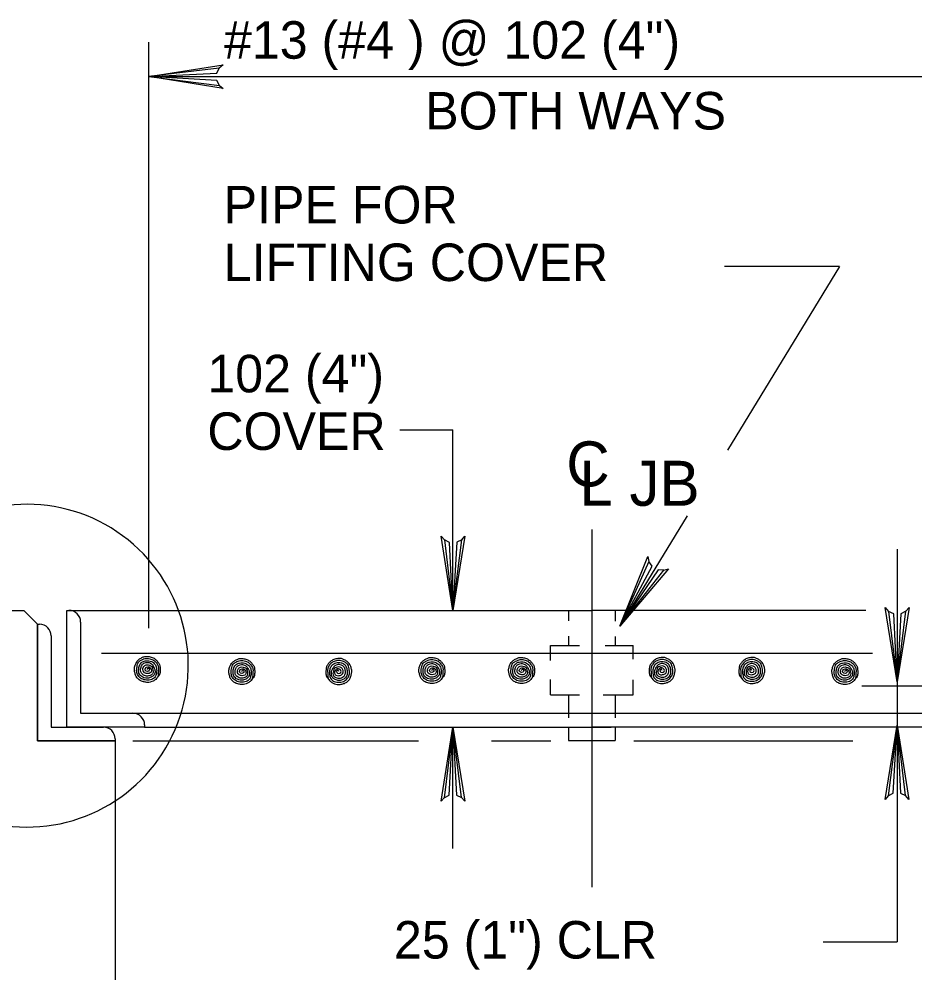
# Model space of a CAD drawing. Extents: x 638455 to 640199, y 298558 to 299152.
# Drawn here: x 638622.1 to 638702.3, y 298765.3 to 298851.3 of the extents above; entities that cross this region are included whole.
import ezdxf

# ---------------------------------------------------------------- set-up
doc = ezdxf.new("R2010")
doc.units = 0
for name, color, linetype in [('1', 7, 'Continuous'), ('2', 7, 'Continuous'), ('3', 7, 'Continuous')]:
    doc.layers.add(name, color=color, linetype=linetype)

msp = doc.modelspace()

# ---------------------------------------------------------------- linework, layer by layer
at = {"layer": '1'}
msp.add_arc((638622.784, 298793.392), 14.456, 185.43869, 133.00871, dxfattribs=at)
at = {"layer": '2'}
for p, q in [((638633.704, 298796.768), (638633.704, 298849.247)), ((638633.704, 298846.161), (638713.153, 298846.161)), ((638695.59, 298829.162), (638685.289, 298829.162)), ((638695.59, 298829.162), (638685.554, 298812.708)), ((638656.187, 298814.519), (638660.96, 298814.519)), ((638660.96, 298798.35), (638660.96, 298814.519)), ((638681.959, 298806.814), (638675.923, 298796.918)), ((638673.404, 298805.586), (638673.404, 298773.557)), ((638700.757, 298803.819), (638700.757, 298791.94)), ((638613.326, 298798.332), (638622.491, 298798.332)), ((638622.491, 298798.332), (638623.722, 298797.101)), ((638626.359, 298798.35), (638626.545, 298798.35)), ((638626.359, 298798.35), (638673.404, 298798.35)), ((638647.242, 298798.35), (638663.399, 298798.35)), ((638671.322, 298798.35), (638671.322, 298797.415)), ((638697.969, 298798.35), (638673.404, 298798.35)), ((638675.485, 298798.35), (638675.485, 298797.372)), ((638623.722, 298797.101), (638623.908, 298797.101)), ((638623.722, 298797.101), (638623.722, 298786.647)), ((638671.322, 298796.038), (638671.322, 298795.198)), ((638669.688, 298793.844), (638669.688, 298795.198)), ((638669.688, 298795.198), (638672.312, 298795.198)), ((638674.591, 298795.198), (638677.119, 298795.198)), ((638675.485, 298795.995), (638675.485, 298795.198)), ((638677.119, 298793.973), (638677.119, 298795.198)), ((638629.46, 298794.517), (638698.566, 298794.517)), ((638669.688, 298790.789), (638669.688, 298792.167)), ((638677.119, 298790.789), (638677.119, 298792.123)), ((638700.757, 298791.94), (638700.757, 298768.654)), ((638697.611, 298791.581), (638703.104, 298791.581)), ((638669.688, 298790.789), (638672.312, 298790.789)), ((638671.322, 298790.789), (638671.322, 298788.725)), ((638674.419, 298790.789), (638677.119, 298790.789)), ((638675.485, 298790.789), (638675.485, 298788.725)), ((638632.283, 298789.127), (638714.524, 298789.127)), ((638633.328, 298788.081), (638633.328, 298787.896)), ((638633.328, 298787.896), (638673.404, 298787.896)), ((638635.768, 298787.896), (638647.886, 298787.896)), ((638654.211, 298787.896), (638663.399, 298787.896)), ((638660.96, 298777.023), (638660.96, 298787.896)), ((638671.322, 298787.896), (638671.322, 298786.682)), ((638671.661, 298787.896), (638675.146, 298787.896)), ((638713.479, 298787.896), (638673.404, 298787.896)), ((638675.485, 298787.896), (638675.485, 298786.682)), ((638623.722, 298786.647), (638630.692, 298786.647)), ((638630.692, 298786.832), (638630.692, 298786.647)), ((638630.692, 298786.647), (638630.692, 298765.256)), ((638632.283, 298786.647), (638657.865, 298786.647)), ((638664.4, 298786.647), (638669.732, 298786.647)), ((638671.322, 298786.682), (638675.485, 298786.682)), ((638677.17, 298786.647), (638696.788, 298786.647)), ((638694.14, 298768.654), (638700.757, 298768.654))]:
    msp.add_line(p, q, dxfattribs=at)
for points in [[(638640.035, 298845.365), (638639.797, 298845.824), (638633.704, 298846.161), (638640.035, 298845.365), (638640.358, 298845.087), (638633.704, 298846.161), (638639.794, 298846.46), (638640.015, 298846.913), (638633.704, 298846.161), (638640.358, 298847.218), (638640.015, 298846.913)], [(638661.756, 298804.678), (638661.297, 298804.442), (638660.96, 298798.35), (638661.756, 298804.678), (638662.034, 298805.003), (638660.96, 298798.35), (638660.661, 298804.44), (638660.205, 298804.66), (638660.96, 298798.35), (638659.903, 298805.003), (638660.205, 298804.66)], [(638679.86, 298801.938), (638679.345, 298801.97), (638675.923, 298796.918), (638679.86, 298801.938), (638680.263, 298802.073), (638675.923, 298796.918), (638678.796, 298802.293), (638678.521, 298802.718), (638675.923, 298796.918), (638678.437, 298803.166), (638678.521, 298802.718)], [(638701.553, 298798.267), (638701.094, 298798.032), (638700.757, 298791.94), (638701.553, 298798.267), (638701.829, 298798.593), (638700.757, 298791.94), (638700.458, 298798.026), (638700.002, 298798.25), (638700.757, 298791.94), (638699.7, 298798.593), (638700.002, 298798.25)], [(638633.328, 298787.896), (638626.359, 298787.896), (638626.359, 298798.35)], [(638630.692, 298786.647), (638623.722, 298786.647), (638623.722, 298797.101)], [(638627.59, 298797.304), (638627.59, 298789.127), (638632.283, 298789.127)], [(638624.953, 298796.056), (638624.953, 298787.878), (638629.647, 298787.878)], [(638660.167, 298781.565), (638660.623, 298781.803), (638660.96, 298787.896), (638660.167, 298781.565), (638659.889, 298781.242), (638660.96, 298787.896), (638661.262, 298781.806), (638661.715, 298781.585), (638660.96, 298787.896), (638662.017, 298781.242), (638661.715, 298781.585)], [(638699.965, 298781.739), (638700.42, 298781.974), (638700.757, 298788.07), (638699.965, 298781.739), (638699.686, 298781.414), (638700.757, 298788.07), (638701.06, 298781.98), (638701.512, 298781.756), (638700.757, 298788.07), (638701.814, 298781.414), (638701.512, 298781.756)]]:
    msp.add_lwpolyline(points, dxfattribs=at)
for centre in [(638626.546, 298797.304), (638623.909, 298796.055), (638632.283, 298788.082), (638629.646, 298786.833)]:
    msp.add_arc(centre, 1.045, 0, 90, dxfattribs=at)
for points in [[(638633.572, 298793.057), (638633.63, 298793.174), (638633.72, 298793.162), (638633.738, 298792.979), (638633.578, 298792.88), (638633.381, 298792.979), (638633.389, 298793.162), (638633.497, 298793.273), (638633.72, 298793.29), (638633.871, 298793.174), (638633.947, 298792.988), (638633.836, 298792.738), (638633.595, 298792.683), (638633.328, 298792.764), (638633.183, 298792.932), (638633.203, 298793.22), (638633.337, 298793.403), (638633.578, 298793.47), (638633.79, 298793.424), (638633.97, 298793.316), (638634.045, 298793.13), (638634.089, 298792.889), (638634.036, 298792.665), (638633.827, 298792.523), (638633.505, 298792.462), (638633.157, 298792.605), (638632.983, 298792.845), (638632.983, 298793.174), (638633.096, 298793.455), (638633.337, 298793.644), (638633.72, 298793.664), (638633.99, 298793.513), (638634.156, 298793.249), (638634.254, 298792.979), (638634.211, 298792.648), (638633.99, 298792.416), (638633.673, 298792.282), (638633.171, 298792.363), (638632.855, 298792.639), (638632.788, 298793.023), (638632.855, 298793.403), (638633.073, 298793.696), (638633.366, 298793.815), (638633.827, 298793.807), (638634.188, 298793.598), (638634.362, 298793.29), (638634.406, 298792.965), (638634.377, 298792.683), (638634.263, 298792.381), (638633.97, 298792.166), (638633.488, 298792.099), (638633.058, 298792.221), (638632.741, 298792.514), (638632.614, 298792.863), (638632.646, 298793.304), (638632.788, 298793.719), (638633.029, 298793.894), (638633.453, 298794.045), (638633.894, 298793.981), (638634.202, 298793.839), (638634.437, 298793.566), (638634.562, 298793.281), (638634.562, 298792.979), (638634.548, 298792.648), (638634.472, 298792.34), (638634.319, 298792.166), (638634.077, 298792.015), (638633.836, 298791.925), (638633.595, 298791.89), (638633.29, 298791.934), (638632.983, 298792.032), (638632.721, 298792.23), (638632.538, 298792.48), (638632.448, 298792.79), (638632.405, 298793.086), (638632.471, 298793.424), (638632.591, 298793.696), (638632.808, 298793.946), (638633.073, 298794.115), (638633.337, 298794.213), (638633.648, 298794.222), (638634.014, 298794.135), (638634.319, 298793.946), (638634.504, 298793.749), (638634.661, 298793.499), (638634.713, 298793.237), (638634.722, 298792.932), (638634.661, 298792.605), (638634.562, 298792.451), (638634.362, 298792.23)], [(638642.04, 298792.869), (638642.098, 298792.985), (638642.188, 298792.973), (638642.206, 298792.79), (638642.046, 298792.692), (638641.848, 298792.79), (638641.857, 298792.973), (638641.964, 298793.084), (638642.188, 298793.101), (638642.339, 298792.985), (638642.415, 298792.799), (638642.304, 298792.549), (638642.063, 298792.494), (638641.796, 298792.575), (638641.651, 298792.744), (638641.671, 298793.028), (638641.805, 298793.211), (638642.046, 298793.281), (638642.258, 298793.235), (638642.438, 298793.127), (638642.513, 298792.941), (638642.557, 298792.7), (638642.505, 298792.477), (638642.295, 298792.335), (638641.973, 298792.271), (638641.625, 298792.416), (638641.451, 298792.654), (638641.451, 298792.985), (638641.564, 298793.266), (638641.805, 298793.452), (638642.188, 298793.476), (638642.458, 298793.325), (638642.624, 298793.061), (638642.723, 298792.79), (638642.679, 298792.459), (638642.458, 298792.227), (638642.142, 298792.093), (638641.639, 298792.175), (638641.323, 298792.451), (638641.256, 298792.834), (638641.323, 298793.211), (638641.54, 298793.507), (638641.834, 298793.627), (638642.295, 298793.618), (638642.656, 298793.409), (638642.83, 298793.101), (638642.874, 298792.776), (638642.841, 298792.494), (638642.731, 298792.192), (638642.438, 298791.977), (638641.956, 298791.91), (638641.526, 298792.03), (638641.209, 298792.326), (638641.082, 298792.674), (638641.114, 298793.116), (638641.256, 298793.531), (638641.497, 298793.702), (638641.921, 298793.856), (638642.362, 298793.792), (638642.67, 298793.65), (638642.905, 298793.377), (638643.03, 298793.092), (638643.03, 298792.79), (638643.016, 298792.459), (638642.94, 298792.151), (638642.786, 298791.977), (638642.545, 298791.826), (638642.304, 298791.736), (638642.063, 298791.701), (638641.758, 298791.745), (638641.451, 298791.843), (638641.189, 298792.038), (638641.006, 298792.288), (638640.916, 298792.602), (638640.872, 298792.895), (638640.939, 298793.235), (638641.059, 298793.507), (638641.276, 298793.757), (638641.54, 298793.926), (638641.805, 298794.024), (638642.115, 298794.033), (638642.481, 298793.943), (638642.786, 298793.757), (638642.972, 298793.56), (638643.129, 298793.31), (638643.181, 298793.049), (638643.19, 298792.744), (638643.129, 298792.416), (638643.03, 298792.262), (638642.83, 298792.038)], [(638650.721, 298792.869), (638650.663, 298792.985), (638650.573, 298792.973), (638650.556, 298792.79), (638650.716, 298792.692), (638650.913, 298792.79), (638650.904, 298792.973), (638650.797, 298793.084), (638650.573, 298793.101), (638650.422, 298792.985), (638650.347, 298792.799), (638650.457, 298792.549), (638650.698, 298792.494), (638650.966, 298792.575), (638651.111, 298792.744), (638651.09, 298793.028), (638650.957, 298793.211), (638650.716, 298793.281), (638650.504, 298793.235), (638650.323, 298793.127), (638650.248, 298792.941), (638650.205, 298792.7), (638650.257, 298792.477), (638650.466, 298792.335), (638650.788, 298792.271), (638651.137, 298792.416), (638651.311, 298792.654), (638651.311, 298792.985), (638651.198, 298793.266), (638650.957, 298793.452), (638650.573, 298793.476), (638650.303, 298793.325), (638650.138, 298793.061), (638650.039, 298792.79), (638650.083, 298792.459), (638650.303, 298792.227), (638650.62, 298792.093), (638651.122, 298792.175), (638651.439, 298792.451), (638651.505, 298792.834), (638651.439, 298793.211), (638651.221, 298793.507), (638650.928, 298793.627), (638650.466, 298793.618), (638650.106, 298793.409), (638649.932, 298793.101), (638649.888, 298792.776), (638649.92, 298792.494), (638650.031, 298792.192), (638650.323, 298791.977), (638650.806, 298791.91), (638651.236, 298792.03), (638651.552, 298792.326), (638651.68, 298792.674), (638651.648, 298793.116), (638651.505, 298793.531), (638651.265, 298793.702), (638650.84, 298793.856), (638650.399, 298793.792), (638650.091, 298793.65), (638649.856, 298793.377), (638649.731, 298793.092), (638649.731, 298792.79), (638649.746, 298792.459), (638649.821, 298792.151), (638649.975, 298791.977), (638650.216, 298791.826), (638650.457, 298791.736), (638650.698, 298791.701), (638651.003, 298791.745), (638651.311, 298791.843), (638651.572, 298792.038), (638651.755, 298792.288), (638651.846, 298792.602), (638651.889, 298792.895), (638651.822, 298793.235), (638651.703, 298793.507), (638651.485, 298793.757), (638651.221, 298793.926), (638650.957, 298794.024), (638650.646, 298794.033), (638650.28, 298793.943), (638649.975, 298793.757), (638649.789, 298793.56), (638649.632, 298793.31), (638649.58, 298793.049), (638649.572, 298792.744), (638649.632, 298792.416), (638649.731, 298792.262), (638649.932, 298792.038)], [(638659.069, 298792.956), (638659.127, 298793.072), (638659.217, 298793.057), (638659.235, 298792.874), (638659.072, 298792.776), (638658.877, 298792.874), (638658.886, 298793.057), (638658.994, 298793.171), (638659.217, 298793.188), (638659.368, 298793.072), (638659.444, 298792.883), (638659.33, 298792.634), (638659.092, 298792.581), (638658.822, 298792.66), (638658.68, 298792.831), (638658.697, 298793.116), (638658.831, 298793.298), (638659.072, 298793.365), (638659.287, 298793.322), (638659.467, 298793.215), (638659.542, 298793.026), (638659.586, 298792.784), (638659.534, 298792.564), (638659.322, 298792.418), (638659.002, 298792.358), (638658.654, 298792.5), (638658.48, 298792.741), (638658.48, 298793.072), (638658.593, 298793.351), (638658.831, 298793.54), (638659.217, 298793.563), (638659.487, 298793.412), (638659.653, 298793.147), (638659.751, 298792.874), (638659.708, 298792.547), (638659.487, 298792.314), (638659.171, 298792.181), (638658.668, 298792.259), (638658.352, 298792.535), (638658.282, 298792.921), (638658.352, 298793.298), (638658.57, 298793.595), (638658.863, 298793.714), (638659.322, 298793.705), (638659.685, 298793.496), (638659.859, 298793.188), (638659.902, 298792.863), (638659.871, 298792.581), (638659.76, 298792.276), (638659.467, 298792.064), (638658.985, 298791.997), (638658.555, 298792.117), (638658.238, 298792.41), (638658.111, 298792.758), (638658.14, 298793.2), (638658.282, 298793.615), (638658.526, 298793.789), (638658.947, 298793.941), (638659.388, 298793.879), (638659.696, 298793.737), (638659.934, 298793.464), (638660.059, 298793.179), (638660.059, 298792.874), (638660.045, 298792.547), (638659.969, 298792.236), (638659.812, 298792.064), (638659.571, 298791.91), (638659.33, 298791.823), (638659.092, 298791.785), (638658.787, 298791.832), (638658.48, 298791.931), (638658.215, 298792.126), (638658.035, 298792.375), (638657.945, 298792.689), (638657.899, 298792.982), (638657.968, 298793.322), (638658.087, 298793.595), (638658.305, 298793.842), (638658.57, 298794.013), (638658.831, 298794.112), (638659.145, 298794.12), (638659.511, 298794.03), (638659.812, 298793.842), (638660.001, 298793.647), (638660.158, 298793.397), (638660.21, 298793.133), (638660.219, 298792.831), (638660.158, 298792.5), (638660.059, 298792.349), (638659.859, 298792.126)], [(638667.107, 298792.956), (638667.165, 298793.072), (638667.256, 298793.057), (638667.273, 298792.874), (638667.113, 298792.776), (638666.916, 298792.874), (638666.924, 298793.057), (638667.032, 298793.171), (638667.256, 298793.188), (638667.407, 298793.072), (638667.482, 298792.883), (638667.372, 298792.634), (638667.131, 298792.581), (638666.863, 298792.66), (638666.721, 298792.831), (638666.739, 298793.116), (638666.872, 298793.298), (638667.113, 298793.365), (638667.328, 298793.322), (638667.505, 298793.215), (638667.581, 298793.026), (638667.627, 298792.784), (638667.572, 298792.564), (638667.363, 298792.418), (638667.041, 298792.358), (638666.695, 298792.5), (638666.521, 298792.741), (638666.521, 298793.072), (638666.631, 298793.351), (638666.872, 298793.54), (638667.256, 298793.563), (638667.528, 298793.412), (638667.694, 298793.147), (638667.79, 298792.874), (638667.746, 298792.547), (638667.528, 298792.314), (638667.212, 298792.181), (638666.706, 298792.259), (638666.39, 298792.535), (638666.323, 298792.921), (638666.39, 298793.298), (638666.608, 298793.595), (638666.904, 298793.714), (638667.363, 298793.705), (638667.723, 298793.496), (638667.897, 298793.188), (638667.944, 298792.863), (638667.912, 298792.581), (638667.798, 298792.276), (638667.505, 298792.064), (638667.023, 298791.997), (638666.596, 298792.117), (638666.28, 298792.41), (638666.149, 298792.758), (638666.181, 298793.2), (638666.323, 298793.615), (638666.564, 298793.789), (638666.989, 298793.941), (638667.43, 298793.879), (638667.737, 298793.737), (638667.973, 298793.464), (638668.098, 298793.179), (638668.098, 298792.874), (638668.086, 298792.547), (638668.011, 298792.236), (638667.854, 298792.064), (638667.613, 298791.91), (638667.372, 298791.823), (638667.131, 298791.785), (638666.829, 298791.832), (638666.521, 298791.931), (638666.257, 298792.126), (638666.074, 298792.375), (638665.983, 298792.689), (638665.94, 298792.982), (638666.007, 298793.322), (638666.126, 298793.595), (638666.346, 298793.842), (638666.608, 298794.013), (638666.872, 298794.112), (638667.183, 298794.12), (638667.549, 298794.03), (638667.854, 298793.842), (638668.04, 298793.647), (638668.196, 298793.397), (638668.252, 298793.133), (638668.26, 298792.831), (638668.196, 298792.5), (638668.098, 298792.349), (638667.897, 298792.126)], [(638679.7, 298792.956), (638679.642, 298793.072), (638679.552, 298793.057), (638679.534, 298792.874), (638679.694, 298792.776), (638679.891, 298792.874), (638679.883, 298793.057), (638679.775, 298793.171), (638679.552, 298793.188), (638679.401, 298793.072), (638679.325, 298792.883), (638679.436, 298792.634), (638679.676, 298792.581), (638679.944, 298792.66), (638680.086, 298792.831), (638680.069, 298793.116), (638679.935, 298793.298), (638679.694, 298793.365), (638679.479, 298793.322), (638679.302, 298793.215), (638679.227, 298793.026), (638679.18, 298792.784), (638679.235, 298792.564), (638679.444, 298792.418), (638679.767, 298792.358), (638680.112, 298792.5), (638680.286, 298792.741), (638680.286, 298793.072), (638680.176, 298793.351), (638679.935, 298793.54), (638679.552, 298793.563), (638679.279, 298793.412), (638679.113, 298793.147), (638679.018, 298792.874), (638679.061, 298792.547), (638679.279, 298792.314), (638679.595, 298792.181), (638680.101, 298792.259), (638680.417, 298792.535), (638680.484, 298792.921), (638680.417, 298793.298), (638680.199, 298793.595), (638679.903, 298793.714), (638679.444, 298793.705), (638679.084, 298793.496), (638678.91, 298793.188), (638678.864, 298792.863), (638678.895, 298792.581), (638679.009, 298792.276), (638679.302, 298792.064), (638679.784, 298791.997), (638680.211, 298792.117), (638680.528, 298792.41), (638680.658, 298792.758), (638680.626, 298793.2), (638680.484, 298793.615), (638680.243, 298793.789), (638679.819, 298793.941), (638679.377, 298793.879), (638679.07, 298793.737), (638678.834, 298793.464), (638678.71, 298793.179), (638678.71, 298792.874), (638678.721, 298792.547), (638678.796, 298792.236), (638678.953, 298792.064), (638679.194, 298791.91), (638679.436, 298791.823), (638679.676, 298791.785), (638679.978, 298791.832), (638680.286, 298791.931), (638680.551, 298792.126), (638680.734, 298792.375), (638680.824, 298792.689), (638680.867, 298792.982), (638680.8, 298793.322), (638680.682, 298793.595), (638680.461, 298793.842), (638680.199, 298794.013), (638679.935, 298794.112), (638679.624, 298794.12), (638679.258, 298794.03), (638678.953, 298793.842), (638678.768, 298793.647), (638678.611, 298793.397), (638678.556, 298793.133), (638678.547, 298792.831), (638678.611, 298792.5), (638678.71, 298792.349), (638678.91, 298792.126)], [(638687.738, 298792.956), (638687.68, 298793.072), (638687.59, 298793.057), (638687.573, 298792.874), (638687.735, 298792.776), (638687.93, 298792.874), (638687.921, 298793.057), (638687.814, 298793.171), (638687.59, 298793.188), (638687.439, 298793.072), (638687.364, 298792.883), (638687.477, 298792.634), (638687.715, 298792.581), (638687.985, 298792.66), (638688.127, 298792.831), (638688.11, 298793.116), (638687.976, 298793.298), (638687.735, 298793.365), (638687.52, 298793.322), (638687.34, 298793.215), (638687.265, 298793.026), (638687.221, 298792.784), (638687.274, 298792.564), (638687.486, 298792.418), (638687.805, 298792.358), (638688.153, 298792.5), (638688.328, 298792.741), (638688.328, 298793.072), (638688.215, 298793.351), (638687.976, 298793.54), (638687.59, 298793.563), (638687.32, 298793.412), (638687.155, 298793.147), (638687.056, 298792.874), (638687.099, 298792.547), (638687.32, 298792.314), (638687.637, 298792.181), (638688.139, 298792.259), (638688.456, 298792.535), (638688.525, 298792.921), (638688.456, 298793.298), (638688.238, 298793.595), (638687.944, 298793.714), (638687.486, 298793.705), (638687.123, 298793.496), (638686.948, 298793.188), (638686.905, 298792.863), (638686.937, 298792.581), (638687.047, 298792.276), (638687.34, 298792.064), (638687.822, 298791.997), (638688.252, 298792.117), (638688.569, 298792.41), (638688.696, 298792.758), (638688.667, 298793.2), (638688.525, 298793.615), (638688.281, 298793.789), (638687.86, 298793.941), (638687.419, 298793.879), (638687.111, 298793.737), (638686.873, 298793.464), (638686.748, 298793.179), (638686.748, 298792.874), (638686.763, 298792.547), (638686.838, 298792.236), (638686.995, 298792.064), (638687.236, 298791.91), (638687.477, 298791.823), (638687.715, 298791.785), (638688.02, 298791.832), (638688.328, 298791.931), (638688.592, 298792.126), (638688.772, 298792.375), (638688.862, 298792.689), (638688.908, 298792.982), (638688.839, 298793.322), (638688.72, 298793.595), (638688.502, 298793.842), (638688.238, 298794.013), (638687.976, 298794.112), (638687.663, 298794.12), (638687.297, 298794.03), (638686.995, 298793.842), (638686.806, 298793.647), (638686.649, 298793.397), (638686.597, 298793.133), (638686.588, 298792.831), (638686.649, 298792.5), (638686.748, 298792.349), (638686.948, 298792.126)], [(638696.086, 298792.869), (638696.144, 298792.985), (638696.234, 298792.973), (638696.251, 298792.79), (638696.092, 298792.692), (638695.894, 298792.79), (638695.903, 298792.973), (638696.01, 298793.084), (638696.234, 298793.101), (638696.385, 298792.985), (638696.46, 298792.799), (638696.35, 298792.549), (638696.109, 298792.494), (638695.842, 298792.575), (638695.696, 298792.744), (638695.717, 298793.028), (638695.85, 298793.211), (638696.092, 298793.281), (638696.304, 298793.235), (638696.484, 298793.127), (638696.559, 298792.941), (638696.603, 298792.7), (638696.551, 298792.477), (638696.341, 298792.335), (638696.019, 298792.271), (638695.671, 298792.416), (638695.496, 298792.654), (638695.496, 298792.985), (638695.609, 298793.266), (638695.85, 298793.452), (638696.234, 298793.476), (638696.504, 298793.325), (638696.669, 298793.061), (638696.768, 298792.79), (638696.725, 298792.459), (638696.504, 298792.227), (638696.188, 298792.093), (638695.685, 298792.175), (638695.368, 298792.451), (638695.302, 298792.834), (638695.368, 298793.211), (638695.586, 298793.507), (638695.88, 298793.627), (638696.341, 298793.618), (638696.702, 298793.409), (638696.876, 298793.101), (638696.919, 298792.776), (638696.887, 298792.494), (638696.777, 298792.192), (638696.484, 298791.977), (638696.001, 298791.91), (638695.572, 298792.03), (638695.255, 298792.326), (638695.127, 298792.674), (638695.159, 298793.116), (638695.302, 298793.531), (638695.542, 298793.702), (638695.967, 298793.856), (638696.408, 298793.792), (638696.716, 298793.65), (638696.951, 298793.377), (638697.076, 298793.092), (638697.076, 298792.79), (638697.061, 298792.459), (638696.986, 298792.151), (638696.832, 298791.977), (638696.591, 298791.826), (638696.35, 298791.736), (638696.109, 298791.701), (638695.804, 298791.745), (638695.496, 298791.843), (638695.235, 298792.038), (638695.052, 298792.288), (638694.962, 298792.602), (638694.918, 298792.895), (638694.985, 298793.235), (638695.104, 298793.507), (638695.322, 298793.757), (638695.586, 298793.926), (638695.85, 298794.024), (638696.161, 298794.033), (638696.527, 298793.943), (638696.832, 298793.757), (638697.018, 298793.56), (638697.175, 298793.31), (638697.227, 298793.049), (638697.236, 298792.744), (638697.175, 298792.416), (638697.076, 298792.262), (638696.876, 298792.038)]]:
    msp.add_spline(points, degree=3, dxfattribs=at)

# ---------------------------------------------------------------- texts
at = {"layer": '3'}
for s, height, p in [('#13 (#4 ) @ 102 (4")', 3.36, (638640.439, 298847.763)), ('BOTH WAYS', 3.36, (638658.47, 298841.426)), ('PIPE FOR', 3.36, (638640.411, 298833.006)), ('LIFTING COVER', 3.36, (638640.411, 298827.846)), ('102 (4")', 3.36, (638638.947, 298817.878)), ('COVER', 3.36, (638638.947, 298812.718)), ('C', 4.032, (638671.114, 298809.451)), ('L JB', 4.032, (638672.28, 298807.716)), ('25 (1") CLR', 3.36, (638655.671, 298767.159))]:
    msp.add_text(s, height=height, dxfattribs=at).set_placement(p)

doc.saveas('drawing.dxf')
